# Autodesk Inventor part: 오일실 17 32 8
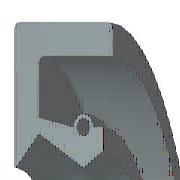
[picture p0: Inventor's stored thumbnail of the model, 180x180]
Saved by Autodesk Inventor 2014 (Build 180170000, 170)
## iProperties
IsCustomPart: 1
Created: 2012-02
Part Number: 오일실 17 32 8
Material: 고무
Description: 오일-실
Document SubType Name: Modeling
Standard: KS B 2804
Designer: mduedu
Standards Organization: KS
Language: ko-KR
Size Designation: D - 17 32 8
Categories: <MemberInstance><Categories><Category DisplayName="샤프트 부품" InternalName="7f7aeb1f-a693-4053-b835-cee3144e0d98" Mnemonic="SHFT"><Category DisplayName="실링" Intern
Density: 0.93 g/cm^3
Mass: 2.28027 g
Surface Area: 32.1224 cm^2
Volume: 2.45191 cm^3
Appearance: 고무 - 검은색 - 버전 1.1
Author: mduedu
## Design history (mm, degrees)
revolve "본체" stored, may be unused: angle "d17" = 90 deg
revolve "스프링1" stored, may be unused: angle "d18" = 90 deg
body "Solid1"
sketch "스케치1"
  geometry: L1 (0, 16)-(8, 16); L2 (8, 14.25)-(1.75, 14.25); L3 (1.75, 10.25)-(4.9, 8.5); L4 (4.9, 8.5)-(0, 8.5); L5 (0, 0)-(9.586, 0) reference; L6 (4.9, 8.5)-(6.3, 9.375); L7 (0, 18)-(0, -3) reference; L8 (-1.941, 0)-(11.507, 0) reference; L9 (4.2, 10.6)-(1.75, 11.21); L10 (1.75, 11.21)-(1.75, 14.25); L11 (0, 16)-(0, 8.588); L12 (4.9, 8.5)-(0, 8.5); L13 (1.75, 10.25)-(0.152, 8.528); L14 (8, 16)-(8, 14.25); L15 (5.6, 10.6)-(6.3, 10.6); L16 (6.3, 10.6)-(6.3, 9.375); C1 r 0.455 at (4.9, 10.6); A1 r 0.7 centre (4.9, 10.6) between (5.6, 10.6) and (4.2, 10.6); A2 r 0.088 centre (0.088, 8.588) between (0, 8.588) and (0.152, 8.528); 1 further point
  constraints: 28 end point, 5 horizontal alignment, 5 point on line, 4 point on circle, 4 vertical alignment, 3 centre point, 3 tangent, 2 collinear, 2 horizontal, 2 perpendicular, 1 coincident, 1 parallel
  dimensions: "d0" = 32 diameter of L1 L5 (= SD2); "d1" = 1.75 distance of L1.end L2.start (= SD); "d2" = 0.91 diameter of C1 (= SPDI); "d3" = 1.4 diameter of A1 (= SPDA); "d4" = 17 diameter of L3.end L5 (= NND); "d5" = 20.5 diameter of L3.start L5 (= TKDM); "d7" = 22.42 diameter of L9.end L5 (= TKDM + 0.24 x SWDT); "d8" = 1.75 distance between parallel lines of L11 L10 (= SD); "d9" = 4.9 distance from line of L11 C1.centre (= SPDST); "d10" = 21.2 diameter of C1.centre L5 (= HLDM); "d11" = 0.0875 radius of A2 (= 0.25 x LAB); "d12" = 6.3 distance between parallel lines of L11 L16 (= SDI); "d13" = 18.75 diameter of L6.end L5 (= ABDM); "d14" = 8 distance from line of L11 L1.end (= SWDT)
fillet "모깎기1" dims "d6" = 0.3 (= RR)
other parameters: "SD2" = 32 [user parameter; used in 1 equation term], "SWDT" = 8 [user parameter; used in 2 equation terms], "RR" = 0.3 [user parameter; used in 1 equation term], "SD" = 1.75 [user parameter; used in 2 equation terms], "NND" = 17 [user parameter; used in 1 equation term], "SPDA" = 1.4 [user parameter; used in 1 equation term], "SPDI" = 0.91 [user parameter; used in 1 equation term], "TKDM" = 20.5 [user parameter; used in 2 equation terms], "HLDM" = 21.2 [user parameter; used in 1 equation term], "ABDM" = 18.75 [user parameter; used in 1 equation term], "SDI" = 6.3 [user parameter; used in 1 equation term], "SPDST" = 4.9 [user parameter; used in 1 equation term], "LAB" = 0.35 [user parameter; used in 1 equation term], "d15" = 0, "d16" = 0, "d19" = 0
